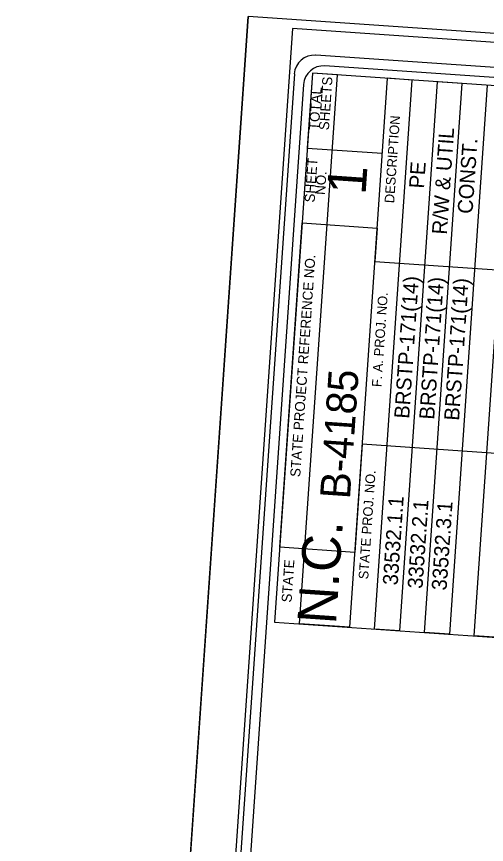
# Model space of a CAD drawing. Extents: x 2598107 to 2605763, y 726018 to 731166.
# Drawn here: x 2598107 to 2598635, y 730235 to 731166 of the extents above; entities that cross this region are included whole.
import ezdxf

# ---------------------------------------------------------------- set-up
doc = ezdxf.new("R2010")
doc.units = 0
for name, color, linetype in [('Sheet Cutting Line CELL', 7, 'Continuous'), ('Sheet Data Field CELL', 7, 'Continuous'), ('Sheet Plot Border Inside CELL', 7, 'Continuous'), ('Sheet Plot Border Outside CELL', 7, 'Continuous'), ('Sheet Title CELL', 7, 'Continuous')]:
    doc.layers.add(name, color=color, linetype=linetype)

msp = doc.modelspace()

# ---------------------------------------------------------------- linework, layer by layer
at = {"layer": 'Sheet Cutting Line CELL'}
msp.add_line((2598106.57, 727386.04), (2598366.91, 731166.08), dxfattribs=at)
at = {"layer": 'Sheet Plot Border Inside CELL'}
msp.add_lwpolyline([(2600527.34, 727248.63), (2600784.97, 730989.4), (2598416.61, 731152.51), (2598158.97, 727411.75)], close=True, dxfattribs=at)
at = {"layer": 'Sheet Plot Border Outside CELL'}
msp.add_lwpolyline([(2598366.91, 731166.08), (2598106.57, 727386.04), (2600575.69, 727215.98), (2600836.03, 730996.03)], close=True, dxfattribs=at)
at = {"layer": 'Sheet Title CELL'}
for points in [[(2600754.84, 730963.28), (2598442.85, 731122.51)], [(2600327.61, 730981.43), (2598453.27, 731110.52)], [(2598418.85, 731101.64), (2598190.02, 727779.46)], [(2598635.59, 731088.94), (2598593.08, 730471.65), (2598565.05, 730473.58), (2598607.53, 731090.87), (2598579.5, 731092.8), (2598536.99, 730475.52), (2598508.93, 730477.45), (2598551.44, 731094.74), (2598523.36, 731096.67), (2598480.84, 730479.38), (2598424.73, 730483.25), (2598467.24, 731100.54), (2598439.18, 731102.47), (2598396.7, 730485.18), (2598733.37, 730461.99)], [(2598775.88, 731079.28), (2598439.18, 731102.47), (2598433.38, 731018.29), (2598517.56, 731012.52)], [(2598429.3, 731089.62), (2598209.78, 727902.2)], [(2598649.22, 730467.81), (2598621.14, 730469.72), (2598663.65, 731087.01)], [(2598747.57, 730667.71), (2598495.04, 730685.11), (2598486.67, 730563.56), (2598402.46, 730569.36), (2598427.62, 730934.14), (2598511.76, 730928.32), (2598509.18, 730890.83), (2598761.71, 730873.44)]]:
    msp.add_lwpolyline(points, dxfattribs=at)
for centre in [(2598441.17, 731100.08), (2598451.62, 731088.09)]:
    msp.add_arc(centre, 22.5, 86.0601, 176.0601, dxfattribs=at)

# ---------------------------------------------------------------- texts
at = {"layer": 'Sheet Data Field CELL'}
for s, height, p in [('R/W & UTIL', 16.875, (2598590.28, 730920.6)), ('CONST.', 16.875, (2598619.04, 730943.85)), ('PE        ', 16.875, (2598564.56, 730972.39)), ('BRSTP-171(14) ', 16.875, (2598547.86, 730713.61)), ('BRSTP-171(14)  ', 16.875, (2598575.98, 730712.56)), ('BRSTP-171(14)  ', 16.875, (2598603.95, 730711.37)), ('B-4185    ', 33.75, (2598481.28, 730622.9)), ('33532.1.1 ', 16.875, (2598534.96, 730526.26)), ('33532.2.1 ', 16.875, (2598562.88, 730522.35)), ('33532.3.1 ', 16.875, (2598589.91, 730520.49))]:
    msp.add_text(s, height=height, rotation=86.0601, dxfattribs=at).set_placement(p)
at = {"layer": 'Sheet Title CELL'}
for s, height, p in [('SHEETS', 11.25, (2598457.63, 731038.02)), ('TOTAL', 11.25, (2598446.36, 731038.04)), ('DESCRIPTION', 10.8, (2598530.95, 730955.98)), ('SHEET', 11.25, (2598441.58, 730956.72)), ('NO.', 11.25, (2598453.3, 730965.27)), ('1', 43.54, (2598498.84, 730964.96)), ('STATE PROJECT REFERENCE NO.', 11.2495, (2598425.39, 730648.07)), ('F. A. PROJ. NO.', 10.8, (2598516.68, 730749.25)), ('STATE PROJ. NO.', 10.8, (2598501.79, 730533.08)), ('N.C.', 43.537, (2598465.58, 730482.13)), ('STATE', 11.25, (2598415.65, 730506.99))]:
    msp.add_text(s, height=height, rotation=86.0601, dxfattribs=at).set_placement(p)

doc.saveas('drawing.dxf')
